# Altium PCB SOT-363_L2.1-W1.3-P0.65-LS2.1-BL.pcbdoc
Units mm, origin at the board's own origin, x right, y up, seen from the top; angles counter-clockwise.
Board outline 15.02 x 15.46 mm, 2 copper layers (Top Layer, Bottom Layer), stack 0 mm thick; 1 components, 0 nets, 6 pads, 0 vias.
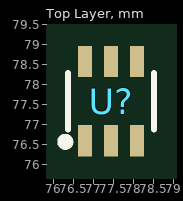
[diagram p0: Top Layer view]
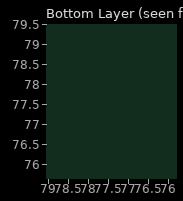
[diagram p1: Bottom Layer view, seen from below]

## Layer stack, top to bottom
Top Layer: signal copper (thickness not stored)
Bottom Layer: signal copper (thickness not stored)

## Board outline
84.869,69.85 69.85,69.85 69.85,85.31 84.869,85.31

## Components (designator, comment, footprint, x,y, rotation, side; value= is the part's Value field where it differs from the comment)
U? "" SOT-363_L2.1-W1.3-P0.65-LS2.1-BL 77.443,77.58 r0 top

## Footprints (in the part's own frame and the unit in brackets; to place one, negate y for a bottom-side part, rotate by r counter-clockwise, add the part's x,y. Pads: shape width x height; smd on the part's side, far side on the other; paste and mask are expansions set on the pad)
SOT-363_L2.1-W1.3-P0.65-LS2.1-BL [mm]
  rect 0.35x0.78 smd: 1(-0.65,-0.99) 2(0,-0.99) 3(0.65,-0.99) 4(0.65,0.99) 5(0,0.99) 6(-0.65,0.99)
  silkscreen extent -1.24,-1.12 1.08,0.7

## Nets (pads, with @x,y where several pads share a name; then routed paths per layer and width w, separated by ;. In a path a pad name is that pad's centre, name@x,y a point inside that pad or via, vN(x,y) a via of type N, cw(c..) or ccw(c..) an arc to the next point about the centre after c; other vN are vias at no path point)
pads on no net: U?.1 U?.2 U?.3 U?.4 U?.5 U?.6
